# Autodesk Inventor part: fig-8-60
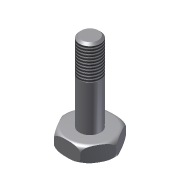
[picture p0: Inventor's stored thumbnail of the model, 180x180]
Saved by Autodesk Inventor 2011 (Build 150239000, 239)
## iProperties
Shininess: 77.0
Length Units: 11269
Angle Units: 11279
Time Units: 11290
Mass Units: 11283
Length Display Precision: 3
Angle Display Precision: 2
Created: 2002-01
Part Number: fig-8-60
Document SubType Name: Modeling
Designer: ***
Density: 1 g/cm^3
Density: 0.0
Volumn: 0.0
Area: 0.0
PropertySet Name: Model Information
Control State: 0
Master: False
Checked Out: False
Author: ***
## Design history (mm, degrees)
sketch "Sketch1"
  geometry: C1 r 25 at (0, 0)
  constraints: 1 centre point
  dimensions: "d0" = 50 diameter of C1
extrude "Extrusion1" new body sketch "Sketch1" distance "d1" = 15; taper "d2" = 0 deg
fillet "Fillet1" dims "d3" = 5
sketch "Sketch2"
  geometry: L1 (25.058, 0)-(12.529, -21.701); L2 (12.529, -21.701)-(-12.529, -21.701); L3 (-12.529, -21.701)-(-25.058, 0); L4 (-25.058, 0)-(-12.529, 21.701); L5 (-12.529, 21.701)-(12.529, 21.701); L6 (12.529, 21.701)-(25.058, 0); 1 further point
  constraints: 12 end point, 11 other
extrude "Extrusion2" sketch "Sketch2" stored distance "d4" = 15; taper "d5" = 0 deg
sketch "Sketch3"
  geometry: C1 r 10.044 at (0, 0); 1 further point
  constraints: 1 centre point, 1 coincident
extrude "Extrusion3" join sketch "Sketch3" distance "d6" = 75; taper "d7" = 0 deg
chamfer "Chamfer1" distance "d8" = 2; stored, may be unused: second distance "d9" = 2, angle "d16" = 45 deg
thread "Thread3" dims "d14" = 30, "d15" = 0
body "Solid1"
